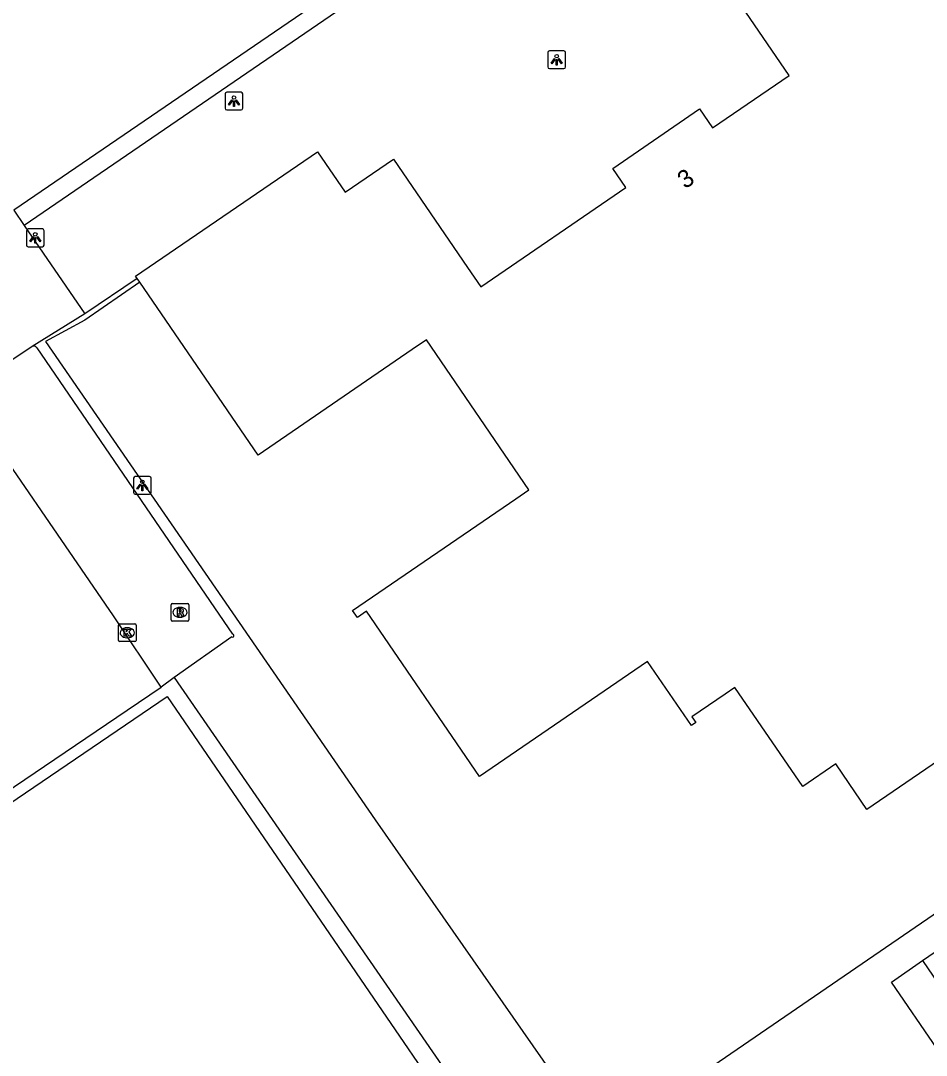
# Model space of a CAD drawing. Extents: x 157466 to 158888, y 383063 to 384677.
# Drawn here: x 158274.5 to 158325.5, y 383661.2 to 383719.4 of the extents above; entities that cross this region are included whole.
import ezdxf

# ---------------------------------------------------------------- set-up
doc = ezdxf.new("R2010")
doc.units = 0
for name, color, linetype in [('IMGEO_Hek', 7, 'Continuous'), ('IMGEO_Kolk', 7, 'Continuous'), ('IMGEO_Lichtpunt', 7, 'Continuous'), ('IMGEO_Pand', 7, 'Continuous'), ('IMGEO_Pand_nummerreeks', 7, 'Continuous'), ('IMGEO_Parkeervlak_open', 7, 'Continuous'), ('IMGEO_Rijbaan_lokaal_gesloten', 7, 'Continuous'), ('IMGEO_Rioolput', 7, 'Continuous'), ('IMGEO_Verkeerseiland_open', 7, 'Continuous'), ('IMGEO_Voetpad_open', 7, 'Continuous')]:
    doc.layers.add(name, color=color, linetype=linetype)

msp = doc.modelspace()

# ---------------------------------------------------------------- linework, layer by layer
at = {"layer": 'IMGEO_Hek'}
for points in [[(158281.192, 383704.728), (158278.101, 383702.589), (158275.89, 383701.379), (158294.448, 383674.456), (158307.144, 383656.25), (158303.112, 383653.504)], [(158281.053, 383704.931), (158278.098, 383702.944)], [(158307.144, 383656.25), (158344.979, 383682.173), (158341.911, 383686.641)]]:
    msp.add_lwpolyline(points, dxfattribs=at)
at = {"layer": 'IMGEO_Kolk'}
for p, q in [((158279.988, 383684.554), (158279.988, 383685.406)), ((158280.063, 383685.48), (158280.915, 383685.48)), ((158280.989, 383685.406), (158280.989, 383684.554)), ((158280.476, 383685.26), (158280.501, 383685.26)), ((158280.915, 383684.48), (158280.063, 383684.48)), ((158280.499, 383684.7), (158280.474, 383684.7))]:
    msp.add_line(p, q, dxfattribs=at)
for points in [[(158279.988, 383684.554), (158279.988, 383685.406)], [(158280.063, 383685.48), (158280.915, 383685.48)], [(158280.989, 383685.406), (158280.989, 383684.554)], [(158280.309, 383685.18), (158280.432, 383685.18), (158280.432, 383685.029), (158280.562, 383685.18), (158280.726, 383685.18), (158280.58, 383685.029), (158280.733, 383684.78), (158280.581, 383684.78), (158280.496, 383684.944), (158280.432, 383684.877), (158280.432, 383684.78), (158280.309, 383684.78), (158280.309, 383685.18)], [(158280.915, 383684.48), (158280.063, 383684.48)]]:
    msp.add_lwpolyline(points, dxfattribs=at)
for centre, start, end in [((158280.065, 383685.404), 91.55205, 178.44795), ((158280.065, 383685.404), 91.55205, 178.44795), ((158280.913, 383685.404), 1.55205, 88.44795), ((158280.913, 383685.404), 1.55205, 88.44795), ((158280.065, 383684.556), 181.55205, 268.44795), ((158280.065, 383684.556), 181.55205, 268.44795), ((158280.913, 383684.556), 271.55205, 358.44795), ((158280.913, 383684.556), 271.55205, 358.44795)]:
    msp.add_arc(centre, 0.0765, start, end, dxfattribs=at)
for centre, major_axis, ratio, start_param, end_param in [((158280.475, 383684.98), (-0.387, 0.002), 0.722429, 4.712389, 7.853982), ((158280.5, 383684.98), (-0.39, 0.002), 0.717154, 1.570796, 4.712389)]:
    msp.add_ellipse(centre, major_axis=major_axis, ratio=ratio, start_param=start_param, end_param=end_param, dxfattribs=at)
at = {"layer": 'IMGEO_Lichtpunt'}
for p, q in [((158304.182, 383717.649), (158304.182, 383716.842)), ((158304.182, 383717.649), (158304.182, 383716.842)), ((158305.084, 383717.744), (158304.276, 383717.744)), ((158305.084, 383717.744), (158304.276, 383717.744)), ((158305.178, 383716.842), (158305.178, 383717.649)), ((158305.178, 383716.842), (158305.178, 383717.649)), ((158304.276, 383716.748), (158305.084, 383716.748)), ((158304.276, 383716.748), (158305.084, 383716.748)), ((158286.003, 383715.321), (158286.003, 383714.514)), ((158286.003, 383715.321), (158286.003, 383714.514)), ((158286.905, 383715.416), (158286.097, 383715.416)), ((158286.905, 383715.416), (158286.097, 383715.416)), ((158286.999, 383714.514), (158286.999, 383715.321)), ((158286.999, 383714.514), (158286.999, 383715.321)), ((158286.097, 383714.42), (158286.905, 383714.42)), ((158286.097, 383714.42), (158286.905, 383714.42)), ((158274.808, 383707.622), (158274.808, 383706.815)), ((158274.808, 383707.622), (158274.808, 383706.815)), ((158275.71, 383707.717), (158274.902, 383707.717)), ((158275.71, 383707.717), (158274.902, 383707.717)), ((158275.804, 383706.815), (158275.804, 383707.622)), ((158275.804, 383706.815), (158275.804, 383707.622)), ((158274.902, 383706.721), (158275.71, 383706.721)), ((158274.902, 383706.721), (158275.71, 383706.721)), ((158280.844, 383693.684), (158280.844, 383692.877)), ((158280.844, 383693.684), (158280.844, 383692.877)), ((158281.746, 383693.779), (158280.938, 383693.779)), ((158281.746, 383693.779), (158280.938, 383693.779)), ((158281.84, 383692.877), (158281.84, 383693.684)), ((158281.84, 383692.877), (158281.84, 383693.684)), ((158280.938, 383692.783), (158281.746, 383692.783)), ((158280.938, 383692.783), (158281.746, 383692.783))]:
    msp.add_line(p, q, dxfattribs=at)
for points in [[(158304.556, 383717.313), (158304.595, 383717.285), (158304.407, 383717.023), (158304.369, 383717.05), (158304.556, 383717.313)], [(158304.658, 383717.265), (158304.705, 383717.265), (158304.705, 383716.943), (158304.658, 383716.943), (158304.658, 383717.265)], [(158304.768, 383717.285), (158304.806, 383717.312), (158304.993, 383717.05), (158304.954, 383717.022), (158304.768, 383717.285)], [(158286.377, 383714.985), (158286.416, 383714.957), (158286.228, 383714.695), (158286.19, 383714.722), (158286.377, 383714.985)], [(158286.479, 383714.937), (158286.526, 383714.937), (158286.526, 383714.615), (158286.479, 383714.615), (158286.479, 383714.937)], [(158286.589, 383714.957), (158286.627, 383714.984), (158286.814, 383714.722), (158286.775, 383714.694), (158286.589, 383714.957)], [(158275.182, 383707.286), (158275.221, 383707.258), (158275.033, 383706.996), (158274.995, 383707.023), (158275.182, 383707.286)], [(158275.284, 383707.238), (158275.331, 383707.238), (158275.331, 383706.916), (158275.284, 383706.916), (158275.284, 383707.238)], [(158275.394, 383707.258), (158275.432, 383707.285), (158275.619, 383707.023), (158275.58, 383706.995), (158275.394, 383707.258)], [(158281.218, 383693.348), (158281.257, 383693.32), (158281.069, 383693.058), (158281.031, 383693.085), (158281.218, 383693.348)], [(158281.32, 383693.3), (158281.367, 383693.3), (158281.367, 383692.978), (158281.32, 383692.978), (158281.32, 383693.3)], [(158281.43, 383693.32), (158281.468, 383693.347), (158281.655, 383693.085), (158281.616, 383693.057), (158281.43, 383693.32)]]:
    msp.add_lwpolyline(points, dxfattribs=at)
for centre in [(158304.681, 383717.447), (158286.502, 383715.119), (158275.307, 383707.42), (158281.343, 383693.482)]:
    msp.add_circle(centre, 0.0994, dxfattribs=at)
for centre, start, end in [((158304.276, 383717.649), 90, 180), ((158304.276, 383717.649), 90, 180), ((158305.084, 383717.649), 0, 90), ((158305.084, 383717.649), 0, 90), ((158304.276, 383716.842), 180, 270), ((158304.276, 383716.842), 180, 270), ((158305.084, 383716.842), 270, 0), ((158305.084, 383716.842), 270, 360), ((158286.097, 383715.321), 90, 180), ((158286.097, 383715.321), 90, 180), ((158286.905, 383715.321), 0, 90), ((158286.905, 383715.321), 0, 90), ((158286.097, 383714.514), 180, 270), ((158286.097, 383714.514), 180, 270), ((158286.905, 383714.514), 270, 0), ((158286.905, 383714.514), 270, 360), ((158274.902, 383707.622), 90, 180), ((158274.902, 383707.622), 90, 180), ((158275.71, 383707.622), 0, 90), ((158275.71, 383707.622), 0, 90), ((158274.902, 383706.815), 180, 270), ((158274.902, 383706.815), 180, 270), ((158275.71, 383706.815), 270, 0), ((158275.71, 383706.815), 270, 360), ((158280.938, 383693.684), 90, 180), ((158280.938, 383693.684), 90, 180), ((158281.746, 383693.684), 0, 90), ((158281.746, 383693.684), 0, 90), ((158280.938, 383692.877), 180, 270), ((158280.938, 383692.877), 180, 270), ((158281.746, 383692.877), 270, 0), ((158281.746, 383692.877), 270, 360)]:
    msp.add_arc(centre, 0.0946, start, end, dxfattribs=at)
at = {"layer": 'IMGEO_Pand'}
for points in [[(158335.028, 383683.84), (158322.155, 383675.032), (158320.791, 383677.026), (158320.404, 383677.591), (158318.541, 383676.316), (158314.719, 383681.902), (158314.176, 383681.53), (158312.303, 383680.249), (158312.522, 383679.929), (158312.269, 383679.756), (158309.797, 383683.369), (158300.335, 383676.894), (158293.974, 383686.189), (158293.452, 383685.833), (158293.178, 383686.234), (158302.375, 383692.528), (158303.12, 383693.038), (158297.343, 383701.481), (158296.532, 383700.926), (158287.856, 383694.989), (158281.192, 383704.728), (158281.053, 383704.931), (158280.962, 383705.064), (158291.198, 383712.069), (158292.759, 383709.787), (158295.485, 383711.653), (158299.656, 383705.557), (158300.406, 383704.461), (158308.578, 383710.053), (158307.842, 383711.129), (158312.734, 383714.476), (158313.464, 383713.409), (158317.781, 383716.363), (158311.956, 383724.875)], [(158248.333, 383658.017), (158282.738, 383681.399), (158301.024, 383654.658)], [(158325.285, 383666.519), (158327.119, 383667.792), (158329.717, 383664.05), (158327.856, 383662.759)], [(158327.856, 383662.759), (158326.105, 383661.544), (158323.534, 383665.304), (158325.285, 383666.519)], [(158325.285, 383666.519), (158327.856, 383662.759)]]:
    msp.add_lwpolyline(points, dxfattribs=at)
at = {"layer": 'IMGEO_Parkeervlak_open'}
for points in [[(158318.912, 383739.463), (158304.262, 383729.417), (158301.094, 383734.058), (158298.373, 383732.165), (158301.564, 383727.539), (158274.095, 383708.785)], [(158275.391, 383701.02), (158286.42, 383684.902)], [(158286.373, 383684.752), (158283.135, 383682.466)]]:
    msp.add_lwpolyline(points, dxfattribs=at)
for centre, radius, start, end in [((158275.222, 383700.925), 0.194, 29.45206, 115.99408), ((158286.419, 383684.82), 0.082, 236.07063, 89.13435)]:
    msp.add_arc(centre, radius, start, end, dxfattribs=at)
at = {"layer": 'IMGEO_Rijbaan_lokaal_gesloten'}
for points in [[(158282.405, 383681.916), (158279.712, 383685.929), (158270.886, 383698.77)], [(158248.368, 383658.778), (158248.432, 383658.827), (158260.795, 383667.305), (158280.477, 383680.616), (158282.405, 383681.916)]]:
    msp.add_lwpolyline(points, dxfattribs=at)
at = {"layer": 'IMGEO_Rioolput'}
for p, q in [((158282.962, 383685.705), (158282.962, 383686.557)), ((158283.037, 383686.631), (158283.889, 383686.631)), ((158283.963, 383686.557), (158283.963, 383685.705)), ((158283.45, 383686.411), (158283.475, 383686.411)), ((158283.889, 383685.631), (158283.037, 383685.631)), ((158283.473, 383685.851), (158283.448, 383685.851))]:
    msp.add_line(p, q, dxfattribs=at)
for points in [[(158282.962, 383685.705), (158282.962, 383686.557)], [(158283.037, 383686.631), (158283.889, 383686.631)], [(158283.963, 383686.557), (158283.963, 383685.705)], [(158283.551, 383686.329), (158283.299, 383686.331), (158283.299, 383685.931)], [(158283.299, 383685.931), (158283.423, 383685.931), (158283.423, 383686.093), (158283.434, 383686.093)], [(158283.477, 383686.25), (158283.423, 383686.25), (158283.423, 383686.169)], [(158283.423, 383686.169), (158283.475, 383686.169)], [(158283.481, 383686.064), (158283.552, 383685.931), (158283.692, 383685.931), (158283.627, 383686.057)], [(158283.889, 383685.631), (158283.037, 383685.631)]]:
    msp.add_lwpolyline(points, dxfattribs=at)
for centre, radius, start, end in [((158283.039, 383686.555), 0.0765, 91.55205, 178.44795), ((158283.039, 383686.555), 0.0765, 91.55205, 178.44795), ((158283.887, 383686.555), 0.0765, 1.55205, 88.44795), ((158283.887, 383686.555), 0.0765, 1.55205, 88.44795), ((158283.433, 383686.04), 0.0533, 26.02933, 88.69889), ((158283.459, 383686.358), 0.19, 274.7715, 282.96867), ((158283.483, 383686.154), 0.0964, 77.00612, 93.18647), ((158283.497, 383686.211), 0.0378, 276.66336, 79.67722), ((158283.55, 383686.219), 0.109, 350.36119, 89.41601), ((158283.548, 383686.219), 0.112, 277.58423, 350.98172), ((158283.532, 383686.004), 0.108, 29.51342, 73.79051), ((158283.039, 383685.707), 0.0765, 181.55205, 268.44795), ((158283.039, 383685.707), 0.0765, 181.55205, 268.44795), ((158283.887, 383685.707), 0.0765, 271.55205, 358.44795), ((158283.887, 383685.707), 0.0765, 271.55205, 358.44795)]:
    msp.add_arc(centre, radius, start, end, dxfattribs=at)
for centre, major_axis, ratio, start_param, end_param in [((158283.449, 383686.131), (-0.387, 0.002), 0.722429, 4.712389, 7.853982), ((158283.474, 383686.131), (-0.39, 0.002), 0.717154, 1.570796, 4.712389)]:
    msp.add_ellipse(centre, major_axis=major_axis, ratio=ratio, start_param=start_param, end_param=end_param, dxfattribs=at)
at = {"layer": 'IMGEO_Verkeerseiland_open'}
msp.add_lwpolyline([(158319.563, 383738.628), (158274.689, 383707.918)], dxfattribs=at)
at = {"layer": 'IMGEO_Voetpad_open'}
for points in [[(158274.095, 383708.785), (158274.689, 383707.918)], [(158274.689, 383707.918), (158278.098, 383702.944), (158275.137, 383701.099)], [(158275.137, 383701.099), (158271.519, 383698.683)], [(158283.135, 383682.466), (158282.405, 383681.916)], [(158283.135, 383682.466), (158301.902, 383655.259)]]:
    msp.add_lwpolyline(points, dxfattribs=at)

# ---------------------------------------------------------------- texts
at = {"layer": 'IMGEO_Pand_nummerreeks'}
msp.add_text('3', height=1, rotation=34.37909, dxfattribs=at).set_placement((158311.916, 383709.942))

doc.saveas('drawing.dxf')
